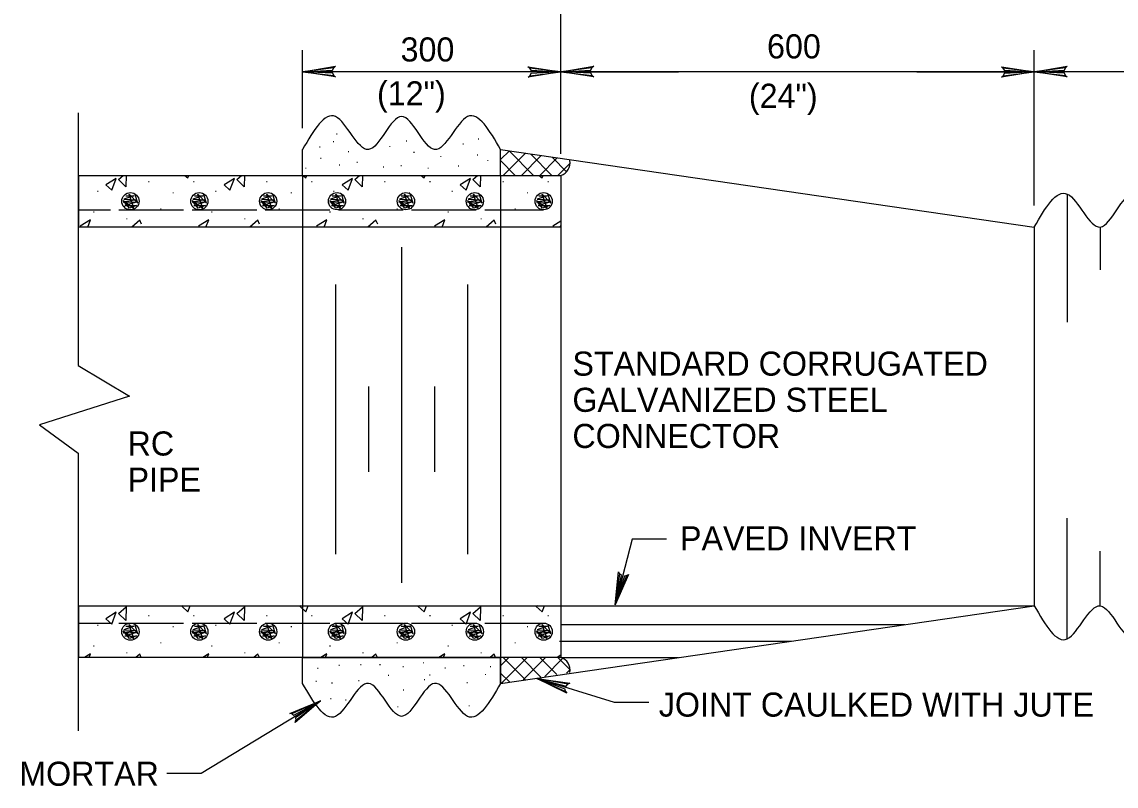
# Model space of a CAD drawing. Extents: x 637898 to 638802, y 298167 to 298761.
# Drawn here: x 638472.4 to 638624.9, y 298593.1 to 298699.6 of the extents above; entities that cross this region are included whole.
import ezdxf

# ---------------------------------------------------------------- set-up
doc = ezdxf.new("R2010")
doc.units = 0
doc.layers.add('2', color=7, linetype='Continuous')
doc.layers.add('3', color=7, linetype='Continuous')

msp = doc.modelspace()

# ---------------------------------------------------------------- linework, layer by layer
at = {"layer": '2'}
for p, q in [((638547.52, 298681.22), (638547.52, 298708.51)), ((638511.52, 298684.82), (638511.52, 298695.66)), ((638547.52, 298681.22), (638547.52, 298695.66)), ((638613.52, 298674.02), (638613.52, 298695.66)), ((638547.52, 298692.66), (638511.52, 298692.66)), ((638597.13, 298692.66), (638547.52, 298692.66)), ((638547.52, 298692.66), (638563.91, 298692.66)), ((638613.52, 298692.66), (638595.52, 298692.66)), ((638597.13, 298692.66), (638613.52, 298692.66)), ((638654.92, 298692.66), (638613.52, 298692.66)), ((638480.22, 298686.95), (638480.22, 298651.72)), ((638511.52, 298678.22), (638511.52, 298681.82)), ((638539.12, 298678.22), (638539.12, 298681.82)), ((638539.12, 298681.82), (638613.52, 298671.02)), ((638511.52, 298678.22), (638511.52, 298611.02)), ((638539.12, 298678.22), (638539.12, 298611.02)), ((638487.99, 298675.37), (638486.61, 298674.9)), ((638486.86, 298675.37), (638487.99, 298675.37)), ((638488.01, 298673.65), (638487.33, 298675.62)), ((638487.33, 298675.62), (638488.53, 298674.34)), ((638488.53, 298674.34), (638488.17, 298675.5)), ((638497.59, 298675.37), (638496.21, 298674.9)), ((638496.46, 298675.37), (638497.59, 298675.37)), ((638497.61, 298673.65), (638496.93, 298675.62)), ((638496.93, 298675.62), (638498.13, 298674.34)), ((638498.13, 298674.34), (638497.77, 298675.5)), ((638507.19, 298675.37), (638505.81, 298674.9)), ((638506.06, 298675.37), (638507.19, 298675.37)), ((638507.21, 298673.65), (638506.53, 298675.62)), ((638506.53, 298675.62), (638507.73, 298674.34)), ((638507.73, 298674.34), (638507.37, 298675.5)), ((638516.79, 298675.37), (638515.41, 298674.9)), ((638515.66, 298675.37), (638516.79, 298675.37)), ((638516.81, 298673.65), (638516.13, 298675.62)), ((638516.13, 298675.62), (638517.33, 298674.34)), ((638517.33, 298674.34), (638516.97, 298675.5)), ((638526.39, 298675.37), (638525.01, 298674.9)), ((638525.26, 298675.37), (638526.39, 298675.37)), ((638526.41, 298673.65), (638525.73, 298675.62)), ((638525.73, 298675.62), (638526.93, 298674.34)), ((638526.93, 298674.34), (638526.57, 298675.5)), ((638535.99, 298675.37), (638534.61, 298674.9)), ((638534.86, 298675.37), (638535.99, 298675.37)), ((638536.01, 298673.65), (638535.33, 298675.62)), ((638535.33, 298675.62), (638536.53, 298674.34)), ((638536.53, 298674.34), (638536.17, 298675.5)), ((638545.59, 298675.37), (638544.21, 298674.9)), ((638544.46, 298675.37), (638545.59, 298675.37)), ((638545.61, 298673.65), (638544.93, 298675.62)), ((638544.93, 298675.62), (638546.13, 298674.34)), ((638546.13, 298674.34), (638545.77, 298675.5)), ((638618.12, 298675.62), (638618.12, 298657.77)), ((638488.3, 298674.8), (638486.52, 298674.47)), ((638487.37, 298673.65), (638486.52, 298674.74)), ((638486.52, 298674.74), (638488.01, 298673.65)), ((638486.52, 298674.47), (638488.5, 298674.54)), ((638486.61, 298674.9), (638488.3, 298674.8)), ((638488.5, 298674.54), (638486.74, 298674)), ((638486.74, 298674), (638488.37, 298674.04)), ((638488.37, 298674.04), (638487.37, 298673.65)), ((638487.52, 298674.62), (638487.52, 298674.62)), ((638487.52, 298674.62), (638487.52, 298674.62)), ((638497.9, 298674.8), (638496.12, 298674.47)), ((638496.97, 298673.65), (638496.12, 298674.74)), ((638496.12, 298674.74), (638497.61, 298673.65)), ((638496.12, 298674.47), (638498.1, 298674.54)), ((638496.21, 298674.9), (638497.9, 298674.8)), ((638498.1, 298674.54), (638496.34, 298674)), ((638496.34, 298674), (638497.97, 298674.04)), ((638497.97, 298674.04), (638496.97, 298673.65)), ((638497.12, 298674.62), (638497.12, 298674.62)), ((638497.12, 298674.62), (638497.12, 298674.62)), ((638507.5, 298674.8), (638505.72, 298674.47)), ((638506.57, 298673.65), (638505.72, 298674.74)), ((638505.72, 298674.74), (638507.21, 298673.65)), ((638505.72, 298674.47), (638507.7, 298674.54)), ((638505.81, 298674.9), (638507.5, 298674.8)), ((638507.7, 298674.54), (638505.94, 298674)), ((638505.94, 298674), (638507.57, 298674.04)), ((638507.57, 298674.04), (638506.57, 298673.65)), ((638506.72, 298674.62), (638506.72, 298674.62)), ((638506.72, 298674.62), (638506.72, 298674.62)), ((638517.1, 298674.8), (638515.32, 298674.47)), ((638516.17, 298673.65), (638515.32, 298674.74)), ((638515.32, 298674.74), (638516.81, 298673.65)), ((638515.32, 298674.47), (638517.3, 298674.54)), ((638515.41, 298674.9), (638517.1, 298674.8)), ((638517.3, 298674.54), (638515.54, 298674)), ((638515.54, 298674), (638517.17, 298674.04)), ((638517.17, 298674.04), (638516.17, 298673.65)), ((638516.32, 298674.62), (638516.32, 298674.62)), ((638516.32, 298674.62), (638516.32, 298674.62)), ((638526.7, 298674.8), (638524.92, 298674.47)), ((638525.77, 298673.65), (638524.92, 298674.74)), ((638524.92, 298674.74), (638526.41, 298673.65)), ((638524.92, 298674.47), (638526.9, 298674.54)), ((638525.01, 298674.9), (638526.7, 298674.8)), ((638526.9, 298674.54), (638525.14, 298674)), ((638525.14, 298674), (638526.77, 298674.04)), ((638526.77, 298674.04), (638525.77, 298673.65)), ((638525.92, 298674.62), (638525.92, 298674.62)), ((638525.92, 298674.62), (638525.92, 298674.62)), ((638536.3, 298674.8), (638534.52, 298674.47)), ((638535.37, 298673.65), (638534.52, 298674.74)), ((638534.52, 298674.74), (638536.01, 298673.65)), ((638534.52, 298674.47), (638536.5, 298674.54)), ((638534.61, 298674.9), (638536.3, 298674.8)), ((638536.5, 298674.54), (638534.74, 298674)), ((638534.74, 298674), (638536.37, 298674.04)), ((638536.37, 298674.04), (638535.37, 298673.65)), ((638535.52, 298674.62), (638535.52, 298674.62)), ((638535.52, 298674.62), (638535.52, 298674.62)), ((638545.9, 298674.8), (638544.12, 298674.47)), ((638544.97, 298673.65), (638544.12, 298674.74)), ((638544.12, 298674.74), (638545.61, 298673.65)), ((638544.12, 298674.47), (638546.1, 298674.54)), ((638544.21, 298674.9), (638545.9, 298674.8)), ((638546.1, 298674.54), (638544.34, 298674)), ((638544.34, 298674), (638545.97, 298674.04)), ((638545.97, 298674.04), (638544.97, 298673.65)), ((638545.12, 298674.62), (638545.12, 298674.62)), ((638545.12, 298674.62), (638545.12, 298674.62)), ((638547.52, 298671.02), (638547.52, 298618.22)), ((638613.52, 298671.02), (638613.52, 298618.22)), ((638622.72, 298671.02), (638622.72, 298665.07)), ((638525.32, 298668.2), (638525.32, 298621.45)), ((638516.12, 298662.99), (638516.12, 298625.41)), ((638534.52, 298662.99), (638534.52, 298625.41)), ((638520.72, 298648.79), (638520.72, 298636.89)), ((638529.92, 298648.79), (638529.92, 298636.89)), ((638480.22, 298639.49), (638480.22, 298600.79)), ((638618.12, 298613.62), (638618.12, 298630.42)), ((638622.72, 298618.22), (638622.72, 298625.83)), ((638539.12, 298607.42), (638613.52, 298618.22)), ((638547.52, 298618.22), (638613.52, 298618.22)), ((638488.01, 298613.65), (638487.33, 298615.62)), ((638487.33, 298615.62), (638488.53, 298614.34)), ((638497.61, 298613.65), (638496.93, 298615.62)), ((638496.93, 298615.62), (638498.13, 298614.34)), ((638507.21, 298613.65), (638506.53, 298615.62)), ((638506.53, 298615.62), (638507.73, 298614.34)), ((638516.81, 298613.65), (638516.13, 298615.62)), ((638516.13, 298615.62), (638517.33, 298614.34)), ((638526.41, 298613.65), (638525.73, 298615.62)), ((638525.73, 298615.62), (638526.93, 298614.34)), ((638536.01, 298613.65), (638535.33, 298615.62)), ((638535.33, 298615.62), (638536.53, 298614.34)), ((638545.61, 298613.65), (638544.93, 298615.62)), ((638544.93, 298615.62), (638546.13, 298614.34)), ((638547.53, 298615.6), (638595.45, 298615.6)), ((638488.3, 298614.8), (638486.52, 298614.47)), ((638487.37, 298613.65), (638486.52, 298614.74)), ((638486.52, 298614.74), (638488.01, 298613.65)), ((638486.52, 298614.47), (638488.5, 298614.54)), ((638487.99, 298615.37), (638486.61, 298614.9)), ((638486.61, 298614.9), (638488.3, 298614.8)), ((638488.5, 298614.54), (638486.74, 298614)), ((638486.86, 298615.37), (638487.99, 298615.37)), ((638487.52, 298614.62), (638487.52, 298614.62)), ((638487.52, 298614.62), (638487.52, 298614.62)), ((638488.53, 298614.34), (638488.17, 298615.5)), ((638497.9, 298614.8), (638496.12, 298614.47)), ((638496.97, 298613.65), (638496.12, 298614.74)), ((638496.12, 298614.74), (638497.61, 298613.65)), ((638496.12, 298614.47), (638498.1, 298614.54)), ((638497.59, 298615.37), (638496.21, 298614.9)), ((638496.21, 298614.9), (638497.9, 298614.8)), ((638498.1, 298614.54), (638496.34, 298614)), ((638496.46, 298615.37), (638497.59, 298615.37)), ((638497.12, 298614.62), (638497.12, 298614.62)), ((638497.12, 298614.62), (638497.12, 298614.62)), ((638498.13, 298614.34), (638497.77, 298615.5)), ((638507.5, 298614.8), (638505.72, 298614.47)), ((638506.57, 298613.65), (638505.72, 298614.74)), ((638505.72, 298614.74), (638507.21, 298613.65)), ((638505.72, 298614.47), (638507.7, 298614.54)), ((638507.19, 298615.37), (638505.81, 298614.9)), ((638505.81, 298614.9), (638507.5, 298614.8)), ((638507.7, 298614.54), (638505.94, 298614)), ((638506.06, 298615.37), (638507.19, 298615.37)), ((638506.72, 298614.62), (638506.72, 298614.62)), ((638506.72, 298614.62), (638506.72, 298614.62)), ((638507.73, 298614.34), (638507.37, 298615.5)), ((638517.1, 298614.8), (638515.32, 298614.47)), ((638516.17, 298613.65), (638515.32, 298614.74)), ((638515.32, 298614.74), (638516.81, 298613.65)), ((638515.32, 298614.47), (638517.3, 298614.54)), ((638516.79, 298615.37), (638515.41, 298614.9)), ((638515.41, 298614.9), (638517.1, 298614.8)), ((638517.3, 298614.54), (638515.54, 298614)), ((638515.66, 298615.37), (638516.79, 298615.37)), ((638516.32, 298614.62), (638516.32, 298614.62)), ((638516.32, 298614.62), (638516.32, 298614.62)), ((638517.33, 298614.34), (638516.97, 298615.5)), ((638526.7, 298614.8), (638524.92, 298614.47)), ((638525.77, 298613.65), (638524.92, 298614.74)), ((638524.92, 298614.74), (638526.41, 298613.65)), ((638524.92, 298614.47), (638526.9, 298614.54)), ((638526.39, 298615.37), (638525.01, 298614.9)), ((638525.01, 298614.9), (638526.7, 298614.8)), ((638526.9, 298614.54), (638525.14, 298614)), ((638525.26, 298615.37), (638526.39, 298615.37)), ((638525.92, 298614.62), (638525.92, 298614.62)), ((638525.92, 298614.62), (638525.92, 298614.62)), ((638526.93, 298614.34), (638526.57, 298615.5)), ((638536.3, 298614.8), (638534.52, 298614.47)), ((638535.37, 298613.65), (638534.52, 298614.74)), ((638534.52, 298614.74), (638536.01, 298613.65)), ((638534.52, 298614.47), (638536.5, 298614.54)), ((638535.99, 298615.37), (638534.61, 298614.9)), ((638534.61, 298614.9), (638536.3, 298614.8)), ((638536.5, 298614.54), (638534.74, 298614)), ((638534.86, 298615.37), (638535.99, 298615.37)), ((638535.52, 298614.62), (638535.52, 298614.62)), ((638535.52, 298614.62), (638535.52, 298614.62)), ((638536.53, 298614.34), (638536.17, 298615.5)), ((638545.9, 298614.8), (638544.12, 298614.47)), ((638544.97, 298613.65), (638544.12, 298614.74)), ((638544.12, 298614.74), (638545.61, 298613.65)), ((638544.12, 298614.47), (638546.1, 298614.54)), ((638545.59, 298615.37), (638544.21, 298614.9)), ((638544.21, 298614.9), (638545.9, 298614.8)), ((638546.1, 298614.54), (638544.34, 298614)), ((638544.46, 298615.37), (638545.59, 298615.37)), ((638545.12, 298614.62), (638545.12, 298614.62)), ((638545.12, 298614.62), (638545.12, 298614.62)), ((638546.13, 298614.34), (638545.77, 298615.5)), ((638486.74, 298614), (638488.37, 298614.04)), ((638488.37, 298614.04), (638487.37, 298613.65)), ((638496.34, 298614), (638497.97, 298614.04)), ((638497.97, 298614.04), (638496.97, 298613.65)), ((638505.94, 298614), (638507.57, 298614.04)), ((638507.57, 298614.04), (638506.57, 298613.65)), ((638515.54, 298614), (638517.17, 298614.04)), ((638517.17, 298614.04), (638516.17, 298613.65)), ((638525.14, 298614), (638526.77, 298614.04)), ((638526.77, 298614.04), (638525.77, 298613.65)), ((638534.74, 298614), (638536.37, 298614.04)), ((638536.37, 298614.04), (638535.37, 298613.65)), ((638544.34, 298614), (638545.97, 298614.04)), ((638545.97, 298614.04), (638544.97, 298613.65)), ((638547.33, 298613.31), (638579.64, 298613.31)), ((638511.52, 298607.42), (638511.52, 298611.02)), ((638539.12, 298607.42), (638539.12, 298611.02)), ((638547.52, 298611.02), (638539.12, 298611.02)), ((638547.52, 298611.02), (638563.92, 298611.02))]:
    msp.add_line(p, q, dxfattribs=at)
for points in [[(638515.88, 298692.14), (638515.72, 298692.46), (638511.52, 298692.66), (638515.88, 298692.14), (638516.11, 298691.95), (638511.52, 298692.66), (638515.71, 298692.9), (638515.86, 298693.21), (638511.52, 298692.66), (638516.1, 298693.42), (638515.86, 298693.21)], [(638543.15, 298693.18), (638543.32, 298692.87), (638547.52, 298692.66), (638543.15, 298693.18), (638542.93, 298693.37), (638547.52, 298692.66), (638543.33, 298692.43), (638543.18, 298692.11), (638547.52, 298692.66), (638542.94, 298691.9), (638543.18, 298692.11)], [(638551.88, 298692.14), (638551.72, 298692.46), (638547.52, 298692.66), (638551.88, 298692.14), (638552.11, 298691.95), (638547.52, 298692.66), (638551.71, 298692.9), (638551.86, 298693.21), (638547.52, 298692.66), (638552.1, 298693.42), (638551.86, 298693.21)], [(638609.15, 298693.18), (638609.32, 298692.87), (638613.52, 298692.66), (638609.15, 298693.18), (638608.93, 298693.37), (638613.52, 298692.66), (638609.33, 298692.43), (638609.18, 298692.11), (638613.52, 298692.66), (638608.94, 298691.9), (638609.18, 298692.11)], [(638617.88, 298692.14), (638617.72, 298692.46), (638613.52, 298692.66), (638617.88, 298692.14), (638618.11, 298691.95), (638613.52, 298692.66), (638617.71, 298692.9), (638617.86, 298693.21), (638613.52, 298692.66), (638618.1, 298693.42), (638617.86, 298693.21)], [(638539.12, 298680.41), (638540.34, 298681.63)], [(638539.48, 298678.22), (638542.54, 298681.29)], [(638543.72, 298678.22), (638540.3, 298681.64)], [(638546.26, 298678.22), (638543.32, 298681.17)], [(638541.17, 298678.22), (638539.12, 298680.28)], [(638542.02, 298678.22), (638544.74, 298680.94)], [(638544.57, 298678.22), (638546.94, 298680.6)], [(638548.32, 298678.71), (638546.34, 298680.69)], [(638547.11, 298678.22), (638548.82, 298679.93)], [(638480.32, 298678.22), (638480.32, 298678.22), (638547.52, 298678.22), (638547.52, 298671.02), (638480.32, 298671.02), (638480.32, 298671.02)], [(638485.86, 298677.65), (638486.53, 298678.22)], [(638486.93, 298678.22), (638486.89, 298676.64)], [(638495.12, 298678.22), (638495.52, 298677.86)], [(638495.52, 298677.86), (638495.66, 298678.22)], [(638502.33, 298677.65), (638502.99, 298678.22)], [(638503.4, 298678.22), (638503.36, 298676.64)], [(638511.58, 298678.22), (638511.99, 298677.86)], [(638511.99, 298677.86), (638512.12, 298678.22)], [(638518.79, 298677.65), (638519.46, 298678.22)], [(638519.86, 298678.22), (638519.82, 298676.64)], [(638528.05, 298678.22), (638528.45, 298677.86)], [(638528.45, 298677.86), (638528.59, 298678.22)], [(638535.25, 298677.65), (638535.92, 298678.22)], [(638536.33, 298678.22), (638536.29, 298676.64)], [(638544.51, 298678.22), (638544.91, 298677.86)], [(638544.91, 298677.86), (638545.05, 298678.22)], [(638486.89, 298676.64), (638485.86, 298677.65)], [(638503.36, 298676.64), (638502.33, 298677.65)], [(638519.82, 298676.64), (638518.79, 298677.65)], [(638536.29, 298676.64), (638535.25, 298677.65)], [(638480.22, 298673.42), (638484.72, 298673.42)], [(638481.96, 298672.02), (638480.52, 298671.12)], [(638481.58, 298671.02), (638481.96, 298672.02)], [(638485.92, 298673.42), (638494.92, 298673.42)], [(638496.12, 298673.42), (638505.12, 298673.42)], [(638498.43, 298672.02), (638496.99, 298671.12)], [(638498.05, 298671.02), (638498.43, 298672.02)], [(638506.32, 298673.42), (638515.32, 298673.42)], [(638514.89, 298672.02), (638513.45, 298671.12)], [(638514.51, 298671.02), (638514.89, 298672.02)], [(638516.52, 298673.42), (638525.52, 298673.42)], [(638526.72, 298673.42), (638535.72, 298673.42)], [(638531.35, 298672.02), (638529.91, 298671.12)], [(638530.97, 298671.02), (638531.35, 298672.02)], [(638536.92, 298673.42), (638545.12, 298673.42)], [(638488.81, 298671.98), (638487.7, 298671.02)], [(638489.07, 298671.41), (638488.81, 298671.98)], [(638505.28, 298671.98), (638504.17, 298671.02)], [(638505.53, 298671.41), (638505.28, 298671.98)], [(638521.74, 298671.98), (638520.63, 298671.02)], [(638521.99, 298671.41), (638521.74, 298671.98)], [(638538.21, 298671.98), (638537.1, 298671.02)], [(638538.46, 298671.41), (638538.21, 298671.98)], [(638547.52, 298671.83), (638546.38, 298671.12)], [(638547.44, 298671.02), (638547.52, 298671.23)], [(638480.22, 298651.72), (638487.38, 298647.43), (638474.86, 298643.46), (638480.22, 298639.49)], [(638562.25, 298627.51), (638557.45, 298627.51), (638555.11, 298618.36)], [(638556.72, 298622.44), (638556.38, 298622.36), (638555.11, 298618.36), (638556.72, 298622.44), (638556.96, 298622.61), (638555.11, 298618.36), (638555.95, 298622.47), (638555.69, 298622.69), (638555.11, 298618.36), (638555.54, 298622.98), (638555.69, 298622.69)], [(638480.32, 298618.22), (638480.32, 298618.22), (638547.52, 298618.22), (638547.52, 298611.02), (638480.32, 298611.02), (638480.32, 298611.02)], [(638494.88, 298618.22), (638494.71, 298618.12)], [(638494.71, 298618.12), (638495.52, 298617.38)], [(638495.52, 298617.38), (638495.84, 298618.22)], [(638511.34, 298618.22), (638511.17, 298618.12)], [(638511.17, 298618.12), (638511.99, 298617.38)], [(638511.99, 298617.38), (638512.31, 298618.22)], [(638527.81, 298618.22), (638527.63, 298618.12)], [(638527.63, 298618.12), (638528.45, 298617.38)], [(638528.45, 298617.38), (638528.77, 298618.22)], [(638544.27, 298618.22), (638544.1, 298618.12)], [(638544.1, 298618.12), (638544.91, 298617.38)], [(638544.91, 298617.38), (638545.24, 298618.22)], [(638480.22, 298615.82), (638484.72, 298615.82)], [(638485.92, 298615.82), (638494.92, 298615.82)], [(638496.12, 298615.82), (638505.12, 298615.82)], [(638506.32, 298615.82), (638515.32, 298615.82)], [(638516.52, 298615.82), (638525.52, 298615.82)], [(638526.72, 298615.82), (638535.72, 298615.82)], [(638536.92, 298615.82), (638545.12, 298615.82)], [(638481.96, 298611.54), (638481.14, 298611.02)], [(638481.77, 298611.02), (638481.96, 298611.54)], [(638488.81, 298611.5), (638488.26, 298611.02)], [(638489.02, 298611.02), (638488.81, 298611.5)], [(638498.43, 298611.54), (638497.6, 298611.02)], [(638498.23, 298611.02), (638498.43, 298611.54)], [(638505.28, 298611.5), (638504.72, 298611.02)], [(638505.49, 298611.02), (638505.28, 298611.5)], [(638511.52, 298607.42), (638511.52, 298611.02), (638539.12, 298611.02), (638539.12, 298607.42)], [(638514.89, 298611.54), (638514.07, 298611.02)], [(638514.69, 298611.02), (638514.89, 298611.54)], [(638521.74, 298611.5), (638521.19, 298611.02)], [(638521.95, 298611.02), (638521.74, 298611.5)], [(638531.35, 298611.54), (638530.53, 298611.02)], [(638531.16, 298611.02), (638531.35, 298611.54)], [(638538.21, 298611.5), (638537.65, 298611.02)], [(638538.42, 298611.02), (638538.21, 298611.5)], [(638539.12, 298609.85), (638540.29, 298611.02)], [(638539.26, 298607.45), (638542.84, 298611.02)], [(638542.55, 298607.96), (638539.48, 298611.02)], [(638544.75, 298608.3), (638542.03, 298611.02)], [(638542.28, 298607.92), (638545.39, 298611.02)], [(638546.95, 298608.65), (638544.57, 298611.02)], [(638547.52, 298611.35), (638546.99, 298611.02)], [(638548.82, 298609.32), (638547.12, 298611.02)], [(638545.3, 298608.39), (638547.81, 298610.91)], [(638540.35, 298607.62), (638539.12, 298608.84)], [(638559.8, 298604.74), (638555, 298604.74), (638544.17, 298608.09)], [(638548.17, 298606.27), (638548.11, 298606.62), (638544.17, 298608.09), (638548.17, 298606.27), (638548.33, 298606.03), (638544.17, 298608.09), (638548.24, 298607.04), (638548.48, 298607.3), (638544.17, 298608.09), (638548.76, 298607.43), (638548.48, 298607.3)], [(638548.31, 298608.86), (638548.82, 298609.37)], [(638492.6, 298594.91), (638497.4, 298594.91), (638514.03, 298604.96)], [(638510.02, 298603.17), (638510.32, 298602.99), (638514.03, 298604.96), (638510.02, 298603.17), (638509.73, 298603.22), (638514.03, 298604.96), (638510.55, 298602.61), (638510.58, 298602.27), (638514.03, 298604.96), (638510.49, 298601.97), (638510.58, 298602.27)]]:
    msp.add_lwpolyline(points, dxfattribs=at)
for points in [[(638480.32, 298671.02), (638480.32, 298678.22), (638547.52, 298678.22), (638547.52, 298671.02)], [(638485.55, 298677.8), (638484.11, 298676.9), (638484.93, 298676.17)], [(638502.01, 298677.8), (638500.57, 298676.9), (638501.39, 298676.17)], [(638518.48, 298677.8), (638517.04, 298676.9), (638517.85, 298676.17)], [(638534.94, 298677.8), (638533.5, 298676.9), (638534.32, 298676.17)], [(638480.32, 298611.02), (638480.32, 298618.22), (638547.52, 298618.22), (638547.52, 298611.02)], [(638485.55, 298617.32), (638484.11, 298616.42), (638484.93, 298615.69)], [(638485.86, 298617.17), (638486.94, 298618.1), (638486.89, 298616.16)], [(638502.01, 298617.32), (638500.57, 298616.42), (638501.39, 298615.69)], [(638502.33, 298617.17), (638503.41, 298618.1), (638503.36, 298616.16)], [(638518.48, 298617.32), (638517.04, 298616.42), (638517.85, 298615.69)], [(638518.79, 298617.17), (638519.87, 298618.1), (638519.82, 298616.16)], [(638534.94, 298617.32), (638533.5, 298616.42), (638534.32, 298615.69)], [(638535.25, 298617.17), (638536.33, 298618.1), (638536.29, 298616.16)]]:
    msp.add_lwpolyline(points, close=True, dxfattribs=at)
for centre in [(638487.52, 298674.62), (638497.12, 298674.62), (638506.72, 298674.62), (638516.32, 298674.62), (638525.92, 298674.62), (638535.52, 298674.62), (638545.12, 298674.62), (638487.52, 298614.62), (638497.12, 298614.62), (638506.72, 298614.62), (638516.32, 298614.62), (638525.92, 298614.62), (638535.52, 298614.62), (638545.12, 298614.62)]:
    msp.add_circle(centre, 1.2, dxfattribs=at)
for centre, start, end in [((638547, 298679.96), 286.4632, 11.0086), ((638547, 298609.28), 348.9914, 73.5368)]:
    msp.add_arc(centre, 1.82, start, end, dxfattribs=at)
for points in [[(638539.12, 298681.82), (638534.52, 298686.42), (638529.92, 298681.82), (638525.32, 298686.42), (638520.72, 298681.82), (638516.12, 298686.42), (638511.52, 298681.82)], [(638613.52, 298671.02), (638618.12, 298675.62), (638622.72, 298671.02), (638627.32, 298675.62), (638631.92, 298671.02), (638636.52, 298675.62), (638641.12, 298671.02), (638645.72, 298675.62), (638650.32, 298671.02), (638654.92, 298675.62)], [(638613.52, 298618.22), (638618.12, 298613.62), (638622.72, 298618.22), (638627.32, 298613.62), (638631.92, 298618.22), (638636.52, 298613.62), (638641.12, 298618.22), (638645.72, 298613.62), (638650.32, 298618.22), (638654.92, 298613.62)], [(638539.12, 298607.42), (638534.52, 298602.82), (638529.92, 298607.42), (638525.32, 298602.82), (638520.72, 298607.42), (638516.12, 298602.82), (638511.52, 298607.42)]]:
    msp.add_spline(points, degree=3, dxfattribs=at)

# ---------------------------------------------------------------- texts
for p in [(638515.6, 298682.83), (638516.08, 298683.89), (638525.81, 298682.94), (638535.83, 298683.19), (638513.72, 298682.09), (638517.7, 298681.43), (638523.45, 298682.16), (638526.84, 298681.35), (638533.69, 298682.49), (638535.68, 298680.98), (638513.87, 298680.5), (638516.45, 298679.58), (638518.92, 298679.95), (638525.07, 298679.47), (638530.56, 298680.76), (638537.12, 298680.21), (638511.77, 298679.14), (638522.6, 298679.29), (638528.83, 298679.14), (638533.03, 298679.44), (638489.86, 298677.26), (638496.15, 298677.26), (638506.32, 298677.26), (638512.61, 298677.26), (638522.79, 298677.26), (638529.07, 298677.26), (638539.25, 298677.26), (638545.54, 298677.26), (638482.75, 298675.91), (638493.28, 298675.7), (638499.22, 298675.91), (638509.74, 298675.7), (638515.68, 298675.91), (638526.21, 298675.7), (638532.15, 298675.91), (638542.67, 298675.7), (638491.56, 298673.46), (638508.03, 298673.46), (638524.49, 298673.46), (638540.95, 298673.46), (638482.2, 298673.03), (638486.8, 298672.07), (638498.67, 298673.03), (638503.26, 298672.07), (638515.13, 298673.03), (638519.73, 298672.07), (638531.59, 298673.03), (638536.19, 298672.07), (638482.75, 298615.43), (638489.86, 298616.78), (638496.15, 298616.78), (638499.22, 298615.43), (638506.32, 298616.78), (638512.61, 298616.78), (638515.68, 298615.43), (638522.79, 298616.78), (638529.07, 298616.78), (638532.15, 298615.43), (638539.25, 298616.78), (638545.54, 298616.78), (638493.28, 298615.22), (638509.74, 298615.22), (638526.21, 298615.22), (638542.67, 298615.22), (638482.2, 298612.55), (638491.56, 298612.98), (638498.67, 298612.55), (638508.03, 298612.98), (638515.13, 298612.55), (638524.49, 298612.98), (638531.59, 298612.55), (638540.95, 298612.98), (638486.8, 298611.59), (638503.26, 298611.59), (638519.73, 298611.59), (638536.19, 298611.59), (638513.42, 298609.43), (638516.42, 298609.85), (638519.41, 298609.95), (638522.1, 298609.92), (638525.33, 298609.64), (638528.16, 298610.19), (638531.19, 298609.46), (638533.8, 298609.81), (638537.49, 298609.64), (638523.28, 298608.45), (638528.3, 298607.86), (638529.06, 298608.49), (638536.79, 298608.56), (638513.21, 298607.62), (638515.41, 298607.37), (638519.13, 298607.72), (638525.37, 298606.4), (638534.25, 298607.44), (638515.23, 298605.21), (638517.32, 298605), (638524.57, 298604.06), (638534.53, 298604.2)]:
    msp.add_text('.', height=1.12, dxfattribs=at).set_placement(p)
at = {"layer": '3'}
for s, p in [('300', (638525.18, 298694.09)), ('600', (638576.26, 298694.52)), ('(12")', (638521.89, 298687.97)), ('(24")', (638573.73, 298687.63)), ('STANDARD CORRUGATED', (638549.13, 298650.3)), ('GALVANIZED STEEL', (638549.13, 298645.26)), ('CONNECTOR', (638549.13, 298640.22)), ('RC', (638487.12, 298639.17)), ('PIPE', (638487.12, 298634.13)), ('PAVED INVERT', (638564.13, 298625.95)), ('JOINT CAULKED WITH JUTE', (638561.17, 298602.78)), ('MORTAR', (638472.02, 298593.14))]:
    msp.add_text(s, height=3.36, dxfattribs=at).set_placement(p)

doc.saveas('drawing.dxf')
